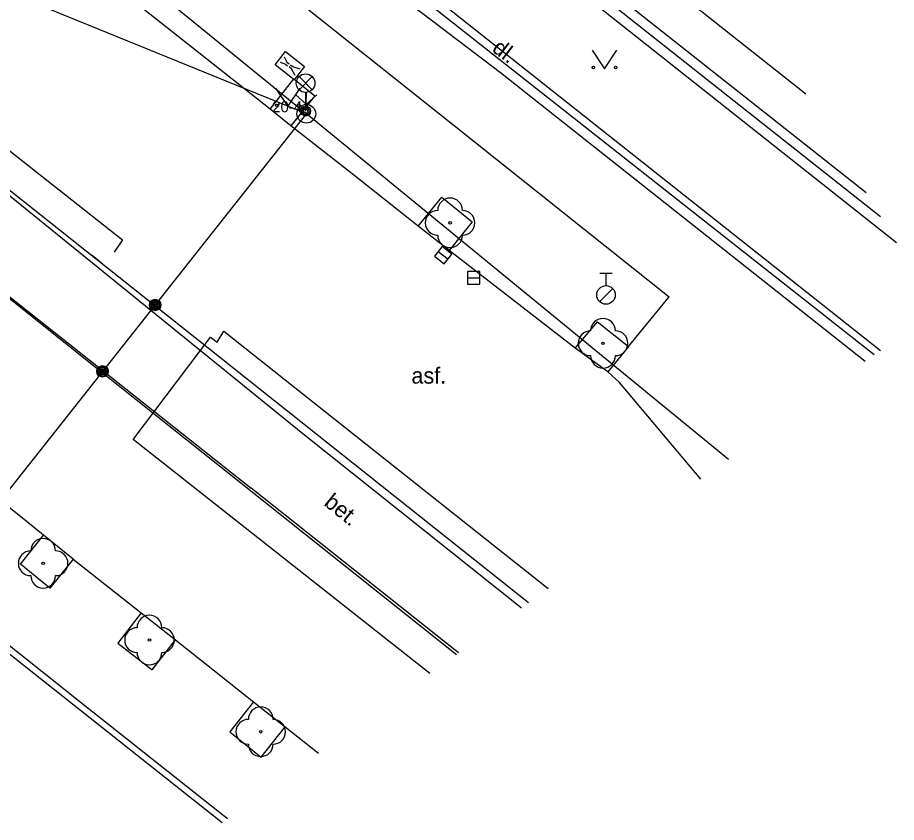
# Model space of a CAD drawing. Extents: x -598168 to -598014, y -1160410 to -1160294.
# Drawn here: x -598049.44 to -598013.98, y -1160398.96 to -1160366.48 of the extents above; entities that cross this region are included whole.
import ezdxf

# ---------------------------------------------------------------- set-up
doc = ezdxf.new("R2010")
doc.units = 0
for name, color, linetype in [('Kabelové vedení_Kabely', 7, 'Continuous'), ('Level 10', 7, 'Continuous'), ('Level 11', 7, 'Continuous'), ('Level 13', 7, 'Continuous'), ('Level 14', 7, 'Continuous'), ('Level 22', 7, 'Continuous'), ('Level 27', 7, 'Continuous'), ('Level 28', 7, 'Continuous'), ('Level 33', 7, 'Continuous'), ('Level 36', 7, 'Continuous'), ('Level 40', 7, 'Continuous'), ('Level 9', 7, 'Continuous'), ('Trolejové vedení_Kotvení', 7, 'Continuous'), ('Trolejové vedení_Nosné lano', 7, 'Continuous'), ('Trolejové vedení_Stožáry', 7, 'Continuous'), ('Trolejové vedení_Trolejový drát', 7, 'Continuous'), ('Trolejové vedení_Zavěšení', 7, 'Continuous')]:
    doc.layers.add(name, color=color, linetype=linetype)

# ---------------------------------------------------------------- blocks, each defined once
blk = doc.blocks.new('TRAKCN')
at = {"layer": 'Trolejové vedení_Stožáry'}
for points in [[(0, 0.0382), (-0.042, 0.0763)], [(-0.0008, 0.0382), (0.0004, 0.0868)], [(0, 0.0386), (0.0421, 0.0768)]]:
    blk.add_lwpolyline(points, dxfattribs=at)
blk.add_circle((0, 0), 0.0378, dxfattribs=at)
blk = doc.blocks.new('ZAVES1')
at = {"layer": 'Trolejové vedení_Zavěšení'}
for points in [[(0, 0), (-0.0035, 0.0035)], [(0, 0), (-0.0035, -0.0035)], [(0, 0), (0.0035, 0.0035)], [(0, 0), (0.0035, -0.0035)]]:
    blk.add_lwpolyline(points, dxfattribs=at)
for radius in [0.0231, 0.0194, 0.0147, 0.00975, 0.00529]:
    blk.add_circle((0, 0), radius, dxfattribs=at)
blk = doc.blocks.new('KOTVEN')
at = {"layer": 'Trolejové vedení_Kotvení'}
blk.add_lwpolyline([(-0.0343, 0.0522), (0.0333, 0.0522), (0.0338, -0.0458), (-0.0343, -0.0455)], close=True, dxfattribs=at)
for points in [[(-0.0158, 0.0443), (-0.0041, 0.0154), (-0.004, 0.0041)], [(0.0172, 0.0445), (0.005, 0.0158), (0.005, 0.0039)], [(-0.0145, -0.0376), (-0.0045, -0.015), (-0.0045, -0.004)], [(0.0131, -0.0362), (0.0052, -0.0148), (0.0051, -0.004)]]:
    blk.add_lwpolyline(points, dxfattribs=at)

msp = doc.modelspace()

# ---------------------------------------------------------------- linework, layer by layer
at = {"layer": 'Kabelové vedení_Kabely'}
for points in [[(-598064.23, -1160360.41), (-598061.37, -1160362.68), (-598045.21, -1160375.45), (-598045.549, -1160375.942)], [(-598046.43, -1160376.06), (-598046.06, -1160376.38)]]:
    msp.add_lwpolyline(points, dxfattribs=at)
at = {"layer": 'Level 10'}
for points in [[(-598039.25, -1160370.17), (-598044.68, -1160365.88)], [(-598038.41, -1160370.84), (-598039.25, -1160370.17)], [(-598033.28, -1160374.89), (-598034.97, -1160373.55), (-598035.76, -1160372.93), (-598038.41, -1160370.84)], [(-598032.03, -1160375.87), (-598033.28, -1160374.89)], [(-598026.94, -1160379.82), (-598032.03, -1160375.87)], [(-598025.63, -1160380.78), (-598026.94, -1160379.82)], [(-598025.15, -1160381.21), (-598025.63, -1160380.78)], [(-598021.869, -1160385.103), (-598025.15, -1160381.21)], [(-598048.39, -1160387.37), (-598051.84, -1160384.6)], [(-598047.2, -1160388.33), (-598048.39, -1160387.37)], [(-598047.2, -1160388.33), (-598044.45, -1160390.5)], [(-598044.45, -1160390.5), (-598043.07, -1160391.59)], [(-598043.07, -1160391.59), (-598039.92, -1160394.09)], [(-598039.92, -1160394.09), (-598038.65, -1160395.1)], [(-598038.65, -1160395.1), (-598037.301, -1160396.169)]]:
    msp.add_lwpolyline(points, dxfattribs=at)
at = {"layer": 'Level 11'}
for points in [[(-598015.249, -1160380.356), (-598029.96, -1160368.7), (-598045.78, -1160356.67), (-598045.52, -1160356.36), (-598045.24, -1160356), (-598042.97, -1160353.13), (-598042.08, -1160352.01)], [(-598042.15, -1160352.72), (-598041.92, -1160352.4), (-598029.4, -1160362.3), (-598019.31, -1160370.3), (-598015.209, -1160373.542)], [(-598042.15, -1160352.72), (-598014.622, -1160374.508)], [(-598042.4, -1160353.03), (-598013.983, -1160375.558)], [(-598044.8, -1160355.99), (-598014.623, -1160379.907)], [(-598014.879, -1160380.091), (-598045.05, -1160356.3)], [(-598047.27, -1160358.57), (-598044.79, -1160360.52), (-598044.21, -1160359.79), (-598040.36, -1160362.83), (-598040.9, -1160363.6), (-598031.83, -1160370.83), (-598023.15, -1160377.74)], [(-598039.25, -1160370.17), (-598038.29, -1160368.95), (-598037.45, -1160369.63), (-598038.41, -1160370.84)], [(-598033.28, -1160374.89), (-598032.32, -1160373.72), (-598031.1, -1160374.72), (-598032.03, -1160375.87)], [(-598024.79, -1160379.75), (-598023.15, -1160377.74)], [(-598026.94, -1160379.82), (-598026.05, -1160378.76), (-598024.79, -1160379.75), (-598025.63, -1160380.78)], [(-598032.802, -1160392.943), (-598044.78, -1160383.51), (-598041.66, -1160379.38), (-598041.39, -1160379.57), (-598041.12, -1160379.13), (-598028.03, -1160389.521)], [(-598055.41, -1160387.33), (-598046.73, -1160394.24), (-598040.975, -1160398.804)], [(-598047.2, -1160388.33), (-598048.14, -1160389.5), (-598049.33, -1160388.54), (-598048.39, -1160387.37)], [(-598044.45, -1160390.5), (-598045.4, -1160391.72), (-598044.01, -1160392.8), (-598043.07, -1160391.59)], [(-598039.92, -1160394.09), (-598040.88, -1160395.3), (-598039.61, -1160396.32), (-598038.65, -1160395.1)]]:
    msp.add_lwpolyline(points, dxfattribs=at)
at = {"layer": 'Level 13'}
for points in [[(-598062.76, -1160363.11), (-598037.93, -1160383.26)], [(-598067.38, -1160363.77), (-598040.02, -1160385.47)], [(-598037.93, -1160383.26), (-598029.109, -1160390.295)], [(-598031.653, -1160392.119), (-598040.02, -1160385.47)]]:
    msp.add_lwpolyline(points, dxfattribs=at)
at = {"layer": 'Level 14'}
msp.add_lwpolyline([(-598030.51, -1160359.36), (-598017.637, -1160369.55)], dxfattribs=at)
at = {"layer": 'Level 22'}
for centre in [(-598031.99, -1160374.76), (-598025.82, -1160379.62), (-598048.41, -1160388.5), (-598044.12, -1160391.6), (-598039.63, -1160395.3)]:
    msp.add_circle(centre, 0.05, dxfattribs=at)
for centre, start, end in [((-598031.99, -1160374.26), 0, 180), ((-598032.49, -1160374.76), 90, 270), ((-598031.49, -1160374.76), 270, 90), ((-598031.99, -1160375.26), 180, 0), ((-598025.82, -1160379.12), 0, 180), ((-598026.32, -1160379.62), 90, 270), ((-598025.32, -1160379.62), 270, 90), ((-598025.82, -1160380.12), 180, 0), ((-598048.41, -1160388), 0, 180), ((-598048.91, -1160388.5), 90, 270), ((-598047.91, -1160388.5), 270, 90), ((-598048.41, -1160389), 180, 0), ((-598044.12, -1160391.1), 0, 180), ((-598044.62, -1160391.6), 90, 270), ((-598043.62, -1160391.6), 270, 90), ((-598044.12, -1160392.1), 180, 0), ((-598039.63, -1160394.8), 0, 180), ((-598040.13, -1160395.3), 90, 270), ((-598039.13, -1160395.3), 270, 90), ((-598039.63, -1160395.8), 180, 0)]:
    msp.add_arc(centre, 0.5, start, end, dxfattribs=at)
at = {"layer": 'Level 27'}
for p, q in [((-598032.466, -1160375.915), (-598032.074, -1160376.225)), ((-598031.29, -1160376.98), (-598030.79, -1160376.98))]:
    msp.add_line(p, q, dxfattribs=at)
for points in [[(-598032.621, -1160376.111), (-598032.229, -1160376.421), (-598031.919, -1160376.029), (-598032.311, -1160375.719)], [(-598031.29, -1160377.23), (-598030.79, -1160377.23), (-598030.79, -1160376.73), (-598031.29, -1160376.73)]]:
    msp.add_lwpolyline(points, close=True, dxfattribs=at)
at = {"layer": 'Level 28'}
for p, q in [((-598025.95, -1160376.795), (-598025.45, -1160376.795)), ((-598025.7, -1160377.295), (-598025.7, -1160376.795)), ((-598025.958, -1160377.942), (-598025.428, -1160377.412))]:
    msp.add_line(p, q, dxfattribs=at)
msp.add_circle((-598025.7, -1160377.67), 0.375, dxfattribs=at)
at = {"layer": 'Level 33'}
for p, q in [((-598038.085, -1160369.39), (-598037.555, -1160368.86)), ((-598038.085, -1160368.86), (-598037.555, -1160369.39)), ((-598037.82, -1160369.5), (-598037.82, -1160370.25))]:
    msp.add_line(p, q, dxfattribs=at)
for centre, radius in [((-598037.82, -1160369.125), 0.375), ((-598037.82, -1160370.25), 0.2), ((-598037.82, -1160370.25), 0.145), ((-598037.82, -1160370.25), 0.0876)]:
    msp.add_circle(centre, radius, dxfattribs=at)
at = {"layer": 'Level 36'}
for points in [[(-598026.26, -1160367.79), (-598025.76, -1160368.54), (-598025.26, -1160367.79)], [(-598039.04, -1160369.32), (-598038.54, -1160370.07), (-598038.04, -1160369.32)]]:
    msp.add_lwpolyline(points, dxfattribs=at)
for centre in [(-598026.21, -1160368.49), (-598025.311, -1160368.49), (-598038.99, -1160370.02), (-598038.091, -1160370.02)]:
    msp.add_circle(centre, 0.05, dxfattribs=at)
at = {"layer": 'Level 9'}
msp.add_lwpolyline([(-598055.23, -1160387.84), (-598041.191, -1160398.959)], dxfattribs=at)
at = {"layer": 'Trolejové vedení_Nosné lano'}
for points in [[(-598052.16, -1160358.64), (-598037.79, -1160370.36)], [(-598052.16, -1160358.64), (-598037.79, -1160370.36)], [(-598037.79, -1160370.36), (-598055.46, -1160363.16)], [(-598037.79, -1160370.36), (-598055.46, -1160363.16)], [(-598050.59, -1160386.54), (-598037.79, -1160370.36)], [(-598050.59, -1160386.54), (-598037.79, -1160370.36)], [(-598020.76, -1160384.308), (-598037.79, -1160370.36)], [(-598020.76, -1160384.308), (-598037.79, -1160370.36)]]:
    msp.add_lwpolyline(points, dxfattribs=at)
at = {"layer": 'Trolejové vedení_Trolejový drát'}
for points in [[(-598058.116, -1160366.803), (-598043.913, -1160378.081)], [(-598060.197, -1160369.482), (-598046.041, -1160380.793)], [(-598043.913, -1160378.081), (-598028.822, -1160390.089)], [(-598046.041, -1160380.793), (-598031.732, -1160392.176)]]:
    msp.add_lwpolyline(points, dxfattribs=at)

# ---------------------------------------------------------------- block references
at = {"layer": 'Trolejové vedení_Kotvení', "xscale": 10, "yscale": 10, "rotation": -128.22247193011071}
msp.add_blockref('KOTVEN', (-598038.482, -1160368.402), dxfattribs=at)
at = {"layer": 'Trolejové vedení_Stožáry', "xscale": 10, "yscale": 10}
msp.add_blockref('TRAKCN', (-598037.79, -1160370.36), dxfattribs=at)
at = {"layer": 'Trolejové vedení_Zavěšení', "xscale": 10, "yscale": 10}
for p in [(-598043.894, -1160378.076), (-598046.011, -1160380.752)]:
    msp.add_blockref('ZAVES1', p, dxfattribs=at)

# ---------------------------------------------------------------- texts
at = {"layer": 'Level 40'}
for s, rotation, p in [('dl.', 322.67, (-598030.34, -1160367.81)), ('bet.', 321.15, (-598037.12, -1160386.13))]:
    msp.add_text(s, height=0.65, rotation=rotation, dxfattribs=at).set_placement(p)
msp.add_text('asf.', height=0.65, dxfattribs=at).set_placement((-598033.55, -1160381.25))
at = {"layer": 'Trolejové vedení_Stožáry'}
msp.add_text('20-4', height=0.45, dxfattribs=at).set_placement((-598039.167, -1160370.3))

doc.saveas('drawing.dxf')
